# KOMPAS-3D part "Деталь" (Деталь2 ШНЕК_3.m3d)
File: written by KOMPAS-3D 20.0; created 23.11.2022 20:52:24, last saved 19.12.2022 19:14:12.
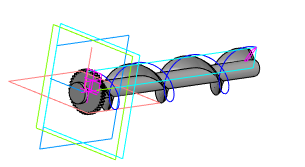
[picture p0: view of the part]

Document properties: Полное имя файла: C:\Users\Семья\Desktop\ДЕТАЛИ ДЛЯ СБОРЩИКА БОРЩЕВИКА\Деталь2 ШНЕК_3.m3d

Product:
- Part/product: Деталь
    Масса: 0.0587114
  - Body: Тело 2
      Масса: 0.0586747
  - Body: Тело 1
      Масса: 0.0586747

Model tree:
1. Эскиз:1
2. Элемент выдавливания:1
     Расстояние 1 = 1
3. Эскиз:3  (with: Элемент выдавливания:1)
4. Элемент выдавливания:4
     Расстояние 1 = 2
5. Эскиз:5  (with: Элемент выдавливания:4)
6. Элемент выдавливания:5
     Расстояние 1 = 114
7. Эскиз:6  (with: Элемент выдавливания:5)
8. Элемент выдавливания:6
     Расстояние 1 = 1
9. Эскиз:7  (with: Элемент выдавливания:4)
10. Спираль:1
     Число витков = 3; Шаг = 38; Высота = 114; Диаметр 1 = 20; Диаметр 2 = 10
11. Плоскость через ребро и точку:1
12. Эскиз:12
13. Элемент выдавливания:9  (with: Элемент выдавливания:1)
     Расстояние 1 = 2
14. Смещенная плоскость:1  (with: ЛСК (Шестерня цилиндрическая с внешними зубьями):1, Шестерня цилиндрическая с внешними зубьями:1, Плоскость XY, Плоскость ZX, Плоскость ZY, Ось X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)  (labels: &Фаска (Шестерня цилиндрическая с внешними зубьями):1)
     Расстояние = 5; Ось X. Y = -1; Ось Y. X = 1; Ось Z. Z = 1; Точка начала. Y = 5; Угол 1 = 360
15. Эскиз для винтовой линии (Шестерня цилиндрическая с внешними зубьями):1  (with: Винтовая линия (Шестерня цилиндрическая с внешними зубьями):1, Шестерня цилиндрическая с внешними зубьями:1, Впадина (Шестерня цилиндрическая с внешними зубьями):1, Впадина прямая (Шестерня цилиндрическая с внешними зубьями):1, Массив косых впадин (Шестерня цилиндрическая с внешними зубьями):1)  (2 pattern instances)
     Число витков = 0.00277425; Смещение 2 = 10
16. Впадина прямая (Шестерня цилиндрическая с внешними зубьями):1  (with: Смещенная плоскость:1, Массив прямых впадин (Шестерня цилиндрическая с внешними зубьями):1, Шестерня цилиндрическая с внешними зубьями:1)  (40 pattern instances)
     N 1 = 1; Шаг 1 = 1; Номер 1 = 1
17. Впадина косая (Шестерня цилиндрическая с внешними зубьями):1  (with: Смещенная плоскость:1, Винтовая линия (Шестерня цилиндрическая с внешними зубьями):1, Впадина прямая (Шестерня цилиндрическая с внешними зубьями):1)  (38 pattern instances)
     N 1 = 1; Шаг 1 = 1; Номер 1 = 1
18. Шестерня цилиндрическая с внешними зубьями:1
19. Элемент выдавливания:24  (with: Элемент выдавливания:4)
     Расстояние 2 = 1
20. Элемент выдавливания:25  (with: Элемент выдавливания:24)
     Расстояние 2 = 1
21. Масштабирование:2
     Коэффициент = 5
22. Масштабирование:3
     Коэффициент = 0.2
23. Масштабирование:4
     Коэффициент = 0.2
24. Эскиз:14  (with: Масштабирование:3)
25. Элемент по траектории:3
26. Эскиз:15  (with: Масштабирование:4)
27. Элемент выдавливания:27
     Расстояние 1 = 10
28. Масштабирование:5
     Коэффициент = 5
29. Масштабирование:6
     Коэффициент = 0.2
30. Элемент выдавливания:28  (with: Масштабирование:6)
     Расстояние 1 = 1
31. Эскиз:16  (with: Элемент выдавливания:28)
32. Элемент выдавливания:29
     Расстояние 1 = 2

Expressions: (VGExtS_1_z*VGExtS_1_M)/COSD(VGExtS_1_Beta); 360/VGExtS_1_z
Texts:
  SHAFT3D
  Количество отображаемых зубьев
  Угол наклона линии зубьев
  Шаг по кольцевому направлению
  (VGExtS_1_Beta>0)?(M_PI*VGExtS_1_z*VGExtS_1_M/SIND(VGExtS_1_Beta)):1000
  (VGExtS_1_Da<=0||VGExtS_1_Da>5e+7)?25:VGExtS_1_Da
  (VGExtS_1_H<=0||VGExtS_1_H>5e+7)?25:VGExtS_1_H
  VGExtS_1_zz<VGExtS_1_z?(VGExtS_1_zz+1):VGExtS_1_z
  (VGExtS_1_zz<=0||VGExtS_1==1)||(VGExtS_1_Beta>0)?1:0
  (VGExtS_1_zz<=0||VGExtS_1==1)||(VGExtS_1_Beta<=0)?1:0
  (VGExtS_1==1)||(VGExtS_1_Beta<=0)?1:0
